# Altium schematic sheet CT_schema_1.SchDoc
size 463 x 258 mm
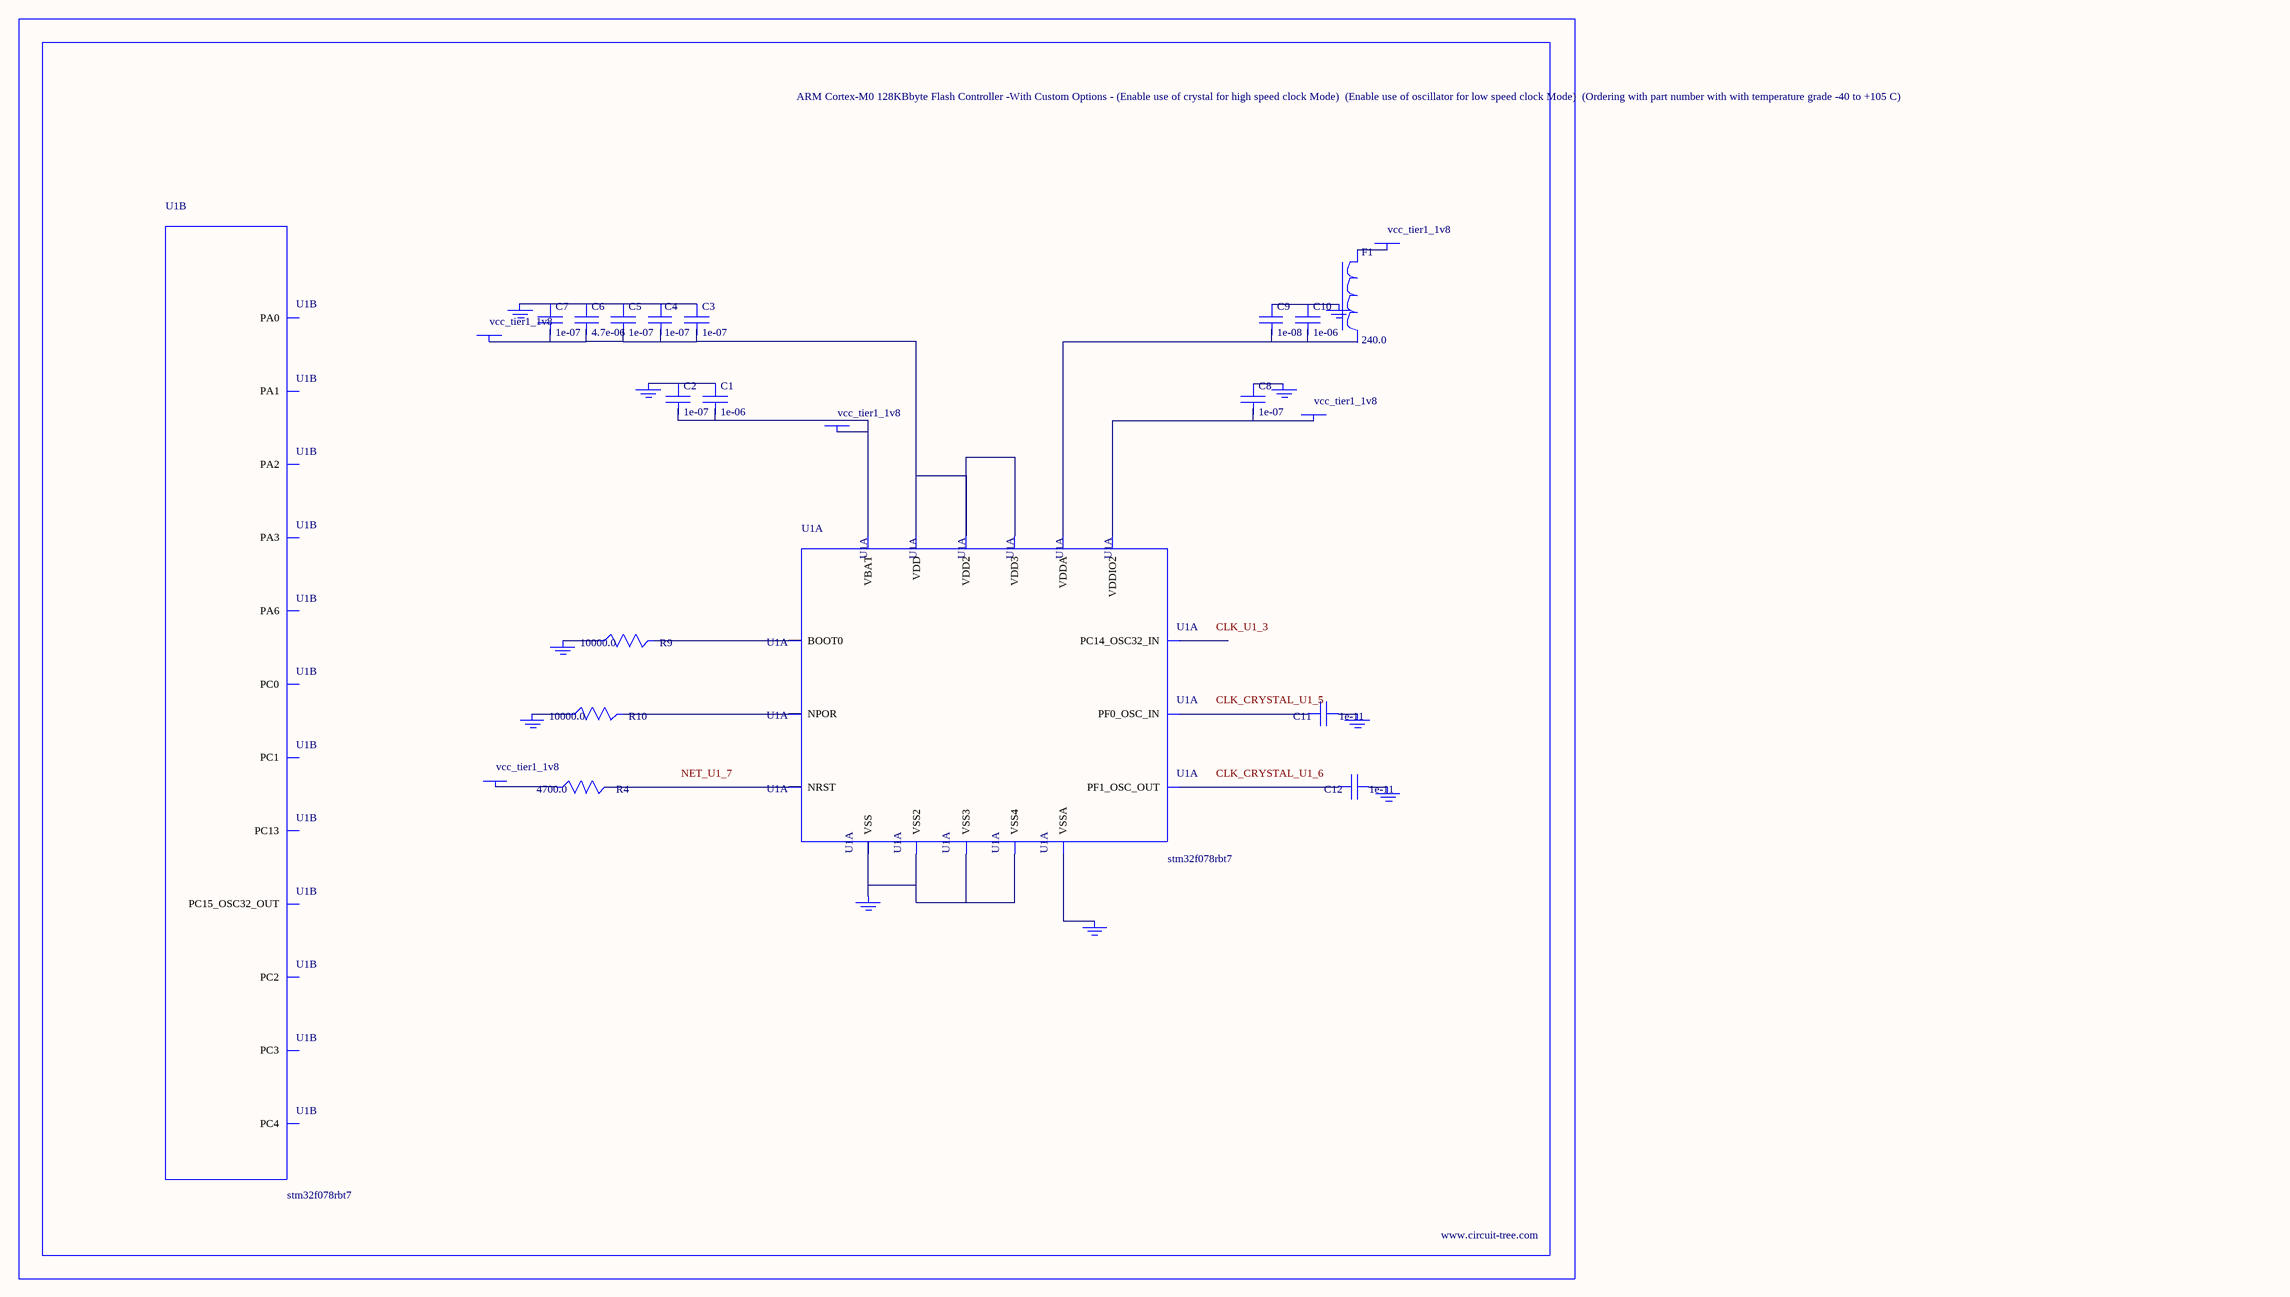
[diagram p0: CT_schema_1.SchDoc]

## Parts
BORDER0  (no value)
C1  1e-06  [C0603]
C2  1e-07  [C0603]
C3  1e-07  [C0603]
C4  1e-07  [C0603]
C5  1e-07  [C0603]
C6  4.7e-06  [C0603]
C7  1e-07  [C0603]
C8  1e-07  [C0603]
C9  1e-08  [C0603]
C10  1e-06  [C0603]
C11  1e-11  [C0402]
C12  1e-11  [C0402]
F1  240.0  [L0603]
GND_INSTANCE_0_0  (no value)
GND_INSTANCE_0_1  (no value)
GND_INSTANCE_0_2  (no value)
GND_INSTANCE_0_3  (no value)
GND_INSTANCE_0_4  (no value)
GND_INSTANCE_0_5  (no value)
GND_INSTANCE_0_6  (no value)
GND_INSTANCE_0_7  (no value)
GND_INSTANCE_0_8  (no value)
GND_INSTANCE_0_9  (no value)
POWER_INSTANCE_0_0  vcc_tier1_1v8
POWER_INSTANCE_0_1  vcc_tier1_1v8
POWER_INSTANCE_0_2  vcc_tier1_1v8
POWER_INSTANCE_0_3  vcc_tier1_1v8
POWER_INSTANCE_0_4  vcc_tier1_1v8
R4  4700.0  [R0603]
R9  10000.0  [R0603]
R10  10000.0  [R0603]
U1  stm32f078rbt7  [LQFP64]  (parts A,B of 7)

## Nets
NetC1_1: C1.1 C2.1 GND_INSTANCE_0_0.0(GND)
NetC1_2: C1.2 C2.2 POWER_INSTANCE_0_0.0(PWR) U1.1(VBAT)
NetC3_1: C3.1 C4.1 C5.1 C6.1 C7.1 GND_INSTANCE_0_5.0(GND)
NetC3_2: C3.2 C4.2 C5.2 C6.2 C7.2 POWER_INSTANCE_0_2.0(PWR) U1.19(VDD) U1.32(VDD2) U1.64(VDD3)
NetC8_1: C8.1 GND_INSTANCE_0_7.0(GND)
NetC8_2: C8.2 POWER_INSTANCE_0_3.0(PWR) U1.48(VDDIO2)
NetC9_1: C9.1 C10.1 GND_INSTANCE_0_4.0(GND)
NetC9_2: C9.2 C10.2 U1.13(VDDA)
NetC11_1: C11.1 GND_INSTANCE_0_1.0(GND)
NetC11_2: C11.2 U1.5(PF0_OSC_IN)
NetC12_1: C12.1 GND_INSTANCE_0_2.0(GND)
NetC12_2: C12.2 U1.6(PF1_OSC_OUT)
NetF1_1: F1.1 POWER_INSTANCE_0_1.0(PWR)
NetGND_INSTANCE_0_3_0: GND_INSTANCE_0_3.0(GND) U1.12(VSSA)
NetGND_INSTANCE_0_6_0: GND_INSTANCE_0_6.0(GND) R10.1
NetGND_INSTANCE_0_8_0: GND_INSTANCE_0_8.0(GND) R9.1
NetGND_INSTANCE_0_9_0: GND_INSTANCE_0_9.0(GND) U1.18(VSS) U1.31(VSS2) U1.47(VSS3) U1.63(VSS4)
NetPOWER_INSTANCE_0_4_0: POWER_INSTANCE_0_4.0(PWR) R4.1
NetR4_2: R4.2 U1.7(NRST)
NetR9_2: R9.2 U1.60(BOOT0)
NetR10_2: R10.2 U1.28(NPOR)

Not connected (* = marked no-connect by the designer): F1 2; U1 2(PC13) 3(PC14_OSC32_IN) 4(PC15_OSC32_OUT) 8(PC0) 9(PC1) 10(PC2) 11(PC3) 14(PA0) 15(PA1) 16(PA2) 17(PA3) 22(PA6) 24(PC4)

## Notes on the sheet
- Labels drawn without touching a wire or pin: CLK_CRYSTAL_U1_5, CLK_CRYSTAL_U1_6, CLK_U1_3, NET_U1_7

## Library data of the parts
BORDER0 = BORDER_PAGE0
C1 C10 = C0603C105K3RACTU
C2-C5 C7 C8 = 06035C104K4Z2A
C6 = GRM188R6YA475KE15D
C9 = 06035C103K4Z2A
C11 C12 = C0402C100K3GACTU
F1 = Z0603C241ASMST
GND_INSTANCE_0_0-GND_INSTANCE_0_9 = GND
POWER_INSTANCE_0_0-POWER_INSTANCE_0_4 = PWR
R4 = RC0603JR-074K7L
R9 R10 = RC0603JR-0710KL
